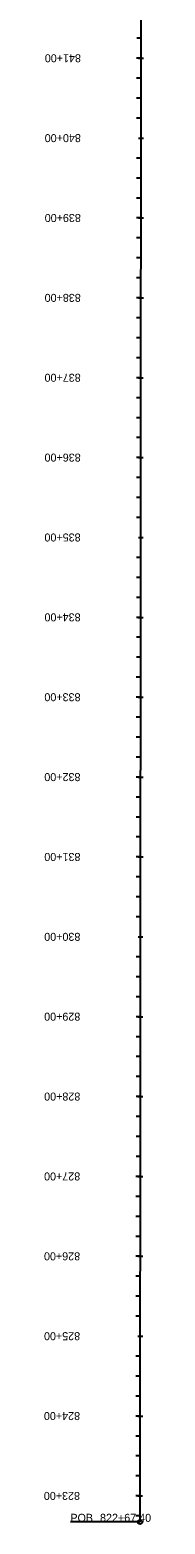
# Model space of a CAD drawing. Extents: x 18543252 to 18543633, y 7433057 to 7440612.
# Drawn here: x 18543264 to 18543397, y 7433057 to 7434928 of the extents above; entities that cross this region are included whole.
import ezdxf

# ---------------------------------------------------------------- set-up
doc = ezdxf.new("R2010")
doc.units = 0
for name, color, linetype in [('PS_BOLT', 7, 'Continuous'), ('PS_DIM', 7, 'Continuous'), ('PS_MID', 7, 'Continuous'), ('PS_SHAPE', 7, 'Continuous')]:
    doc.layers.add(name, color=color, linetype=linetype)

msp = doc.modelspace()

# ---------------------------------------------------------------- linework, layer by layer
at = {"layer": 'PS_BOLT'}
for p, q in [((18543384.8, 7434892.4), (18543379.3, 7434892.4)), ((18543381.7, 7434792.4), (18543387.8, 7434792.4)), ((18543384.7, 7434692.4), (18543379.2, 7434692.4)), ((18543384.6, 7434592.4), (18543379.1, 7434592.4)), ((18543384.5, 7434492.4), (18543379.1, 7434492.4)), ((18543384.5, 7434392.4), (18543379, 7434392.4)), ((18543381.4, 7434292.4), (18543387.5, 7434292.4)), ((18543384.3, 7434192.4), (18543378.9, 7434192.4)), ((18543384.3, 7434092.4), (18543378.8, 7434092.4)), ((18543384.2, 7433992.4), (18543378.8, 7433992.4)), ((18543384.2, 7433892.4), (18543378.7, 7433892.4)), ((18543381, 7433792.4), (18543387.1, 7433792.4)), ((18543384, 7433692.4), (18543378.6, 7433692.4)), ((18543384, 7433592.4), (18543378.5, 7433592.4)), ((18543383.9, 7433492.4), (18543378.4, 7433492.4)), ((18543383.8, 7433392.4), (18543378.4, 7433392.4)), ((18543380.7, 7433292.4), (18543386.8, 7433292.4)), ((18543383.7, 7433192.4), (18543378.2, 7433192.4)), ((18543383.6, 7433092.4), (18543378.2, 7433092.4))]:
    msp.add_line(p, q, dxfattribs=at)
at = {"layer": 'PS_DIM'}
msp.add_line((18543383.6, 7433059.8), (18543296.6, 7433059.8), dxfattribs=at)
msp.add_circle((18543383.6, 7433059.8), 2.67, dxfattribs=at)
at = {"layer": 'PS_MID'}
for p, q in [((18543384.8, 7434917.4), (18543379.4, 7434917.4)), ((18543381.7, 7434892.4), (18543387.9, 7434892.4)), ((18543384.8, 7434867.4), (18543379.3, 7434867.4)), ((18543384.8, 7434842.4), (18543379.3, 7434842.4)), ((18543384.8, 7434817.4), (18543379.3, 7434817.4)), ((18543381.7, 7434792.4), (18543387.8, 7434792.4)), ((18543384.7, 7434767.4), (18543379.3, 7434767.4)), ((18543384.7, 7434742.4), (18543379.2, 7434742.4)), ((18543384.7, 7434717.4), (18543379.2, 7434717.4)), ((18543381.6, 7434692.4), (18543387.7, 7434692.4)), ((18543384.7, 7434667.4), (18543379.2, 7434667.4)), ((18543384.6, 7434642.4), (18543379.2, 7434642.4)), ((18543384.6, 7434617.4), (18543379.2, 7434617.4)), ((18543381.5, 7434592.4), (18543387.7, 7434592.4)), ((18543384.6, 7434567.4), (18543379.1, 7434567.4)), ((18543384.6, 7434542.4), (18543379.1, 7434542.4)), ((18543384.6, 7434517.4), (18543379.1, 7434517.4)), ((18543381.5, 7434492.4), (18543387.6, 7434492.4)), ((18543384.5, 7434467.4), (18543379.1, 7434467.4)), ((18543384.5, 7434442.4), (18543379.1, 7434442.4)), ((18543384.5, 7434417.4), (18543379, 7434417.4)), ((18543381.4, 7434392.4), (18543387.5, 7434392.4)), ((18543384.5, 7434367.4), (18543379, 7434367.4)), ((18543384.4, 7434342.4), (18543379, 7434342.4)), ((18543384.4, 7434317.4), (18543379, 7434317.4)), ((18543381.4, 7434292.4), (18543387.5, 7434292.4)), ((18543384.4, 7434267.4), (18543378.9, 7434267.4)), ((18543384.4, 7434242.4), (18543378.9, 7434242.4)), ((18543384.4, 7434217.4), (18543378.9, 7434217.4)), ((18543381.3, 7434192.4), (18543387.4, 7434192.4)), ((18543384.3, 7434167.4), (18543378.9, 7434167.4)), ((18543384.3, 7434142.4), (18543378.9, 7434142.4)), ((18543384.3, 7434117.4), (18543378.8, 7434117.4)), ((18543381.2, 7434092.4), (18543387.3, 7434092.4)), ((18543384.3, 7434067.4), (18543378.8, 7434067.4)), ((18543384.3, 7434042.4), (18543378.8, 7434042.4)), ((18543384.2, 7434017.4), (18543378.8, 7434017.4)), ((18543381.2, 7433992.4), (18543387.3, 7433992.4)), ((18543384.2, 7433967.4), (18543378.7, 7433967.4)), ((18543384.2, 7433942.4), (18543378.7, 7433942.4)), ((18543384.2, 7433917.4), (18543378.7, 7433917.4)), ((18543381.1, 7433892.4), (18543387.2, 7433892.4)), ((18543384.1, 7433867.4), (18543378.7, 7433867.4)), ((18543384.1, 7433842.4), (18543378.7, 7433842.4)), ((18543384.1, 7433817.4), (18543378.6, 7433817.4)), ((18543381, 7433792.4), (18543387.1, 7433792.4)), ((18543384.1, 7433767.4), (18543378.6, 7433767.4)), ((18543384.1, 7433742.4), (18543378.6, 7433742.4)), ((18543384, 7433717.4), (18543378.6, 7433717.4)), ((18543381, 7433692.4), (18543387.1, 7433692.4)), ((18543384, 7433667.4), (18543378.5, 7433667.4)), ((18543384, 7433642.4), (18543378.5, 7433642.4)), ((18543384, 7433617.4), (18543378.5, 7433617.4)), ((18543380.9, 7433592.4), (18543387, 7433592.4)), ((18543383.9, 7433567.4), (18543378.5, 7433567.4)), ((18543383.9, 7433542.4), (18543378.5, 7433542.4)), ((18543383.9, 7433517.4), (18543378.5, 7433517.4)), ((18543380.8, 7433492.4), (18543387, 7433492.4)), ((18543383.9, 7433467.4), (18543378.4, 7433467.4)), ((18543383.9, 7433442.4), (18543378.4, 7433442.4)), ((18543383.8, 7433417.4), (18543378.4, 7433417.4)), ((18543380.8, 7433392.4), (18543386.9, 7433392.4)), ((18543383.8, 7433367.4), (18543378.4, 7433367.4)), ((18543383.8, 7433342.4), (18543378.3, 7433342.4)), ((18543383.8, 7433317.4), (18543378.3, 7433317.4)), ((18543380.7, 7433292.4), (18543386.8, 7433292.4)), ((18543383.7, 7433267.4), (18543378.3, 7433267.4)), ((18543383.7, 7433242.4), (18543378.3, 7433242.4)), ((18543383.7, 7433217.4), (18543378.3, 7433217.4)), ((18543380.6, 7433192.4), (18543386.8, 7433192.4)), ((18543383.7, 7433167.4), (18543378.2, 7433167.4)), ((18543383.7, 7433142.4), (18543378.2, 7433142.4)), ((18543383.7, 7433117.4), (18543378.2, 7433117.4)), ((18543380.6, 7433092.4), (18543386.7, 7433092.4)), ((18543383.6, 7433067.4), (18543378.2, 7433067.4))]:
    msp.add_line(p, q, dxfattribs=at)
at = {"layer": 'PS_SHAPE'}
msp.add_line((18543383.6, 7433059.8), (18543384.8, 7434941.6), dxfattribs=at)

# ---------------------------------------------------------------- texts
at = {"layer": 'PS_BOLT'}
for s, p in [('840+00', (18543309.7, 7434797.4)), ('835+00', (18543309.4, 7434297.4)), ('830+00', (18543309.1, 7433797.4)), ('825+00', (18543308.8, 7433297.4))]:
    msp.add_text(s, height=10.02, rotation=179.9628, dxfattribs=at).set_placement(p)
at = {"layer": 'PS_DIM'}
for s, p in [('POB ', (18543296.6, 7433060)), ('822+67.40', (18543333.6, 7433060))]:
    msp.add_text(s, height=10.02, rotation=359.9628, dxfattribs=at).set_placement(p)
at = {"layer": 'PS_MID'}
for s, p in [('841+00', (18543309.8, 7434897.4)), ('840+00', (18543309.7, 7434797.4)), ('839+00', (18543309.7, 7434697.4)), ('838+00', (18543309.6, 7434597.4)), ('837+00', (18543309.5, 7434497.4)), ('836+00', (18543309.5, 7434397.4)), ('835+00', (18543309.4, 7434297.4)), ('834+00', (18543309.4, 7434197.4)), ('833+00', (18543309.3, 7434097.4)), ('832+00', (18543309.2, 7433997.4)), ('831+00', (18543309.2, 7433897.4)), ('830+00', (18543309.1, 7433797.4)), ('829+00', (18543309, 7433697.4)), ('828+00', (18543309, 7433597.4)), ('827+00', (18543308.9, 7433497.4)), ('826+00', (18543308.8, 7433397.4)), ('825+00', (18543308.8, 7433297.4)), ('824+00', (18543308.7, 7433197.4)), ('823+00', (18543308.6, 7433097.4))]:
    msp.add_text(s, height=10.02, rotation=179.9628, dxfattribs=at).set_placement(p)

doc.saveas('drawing.dxf')
